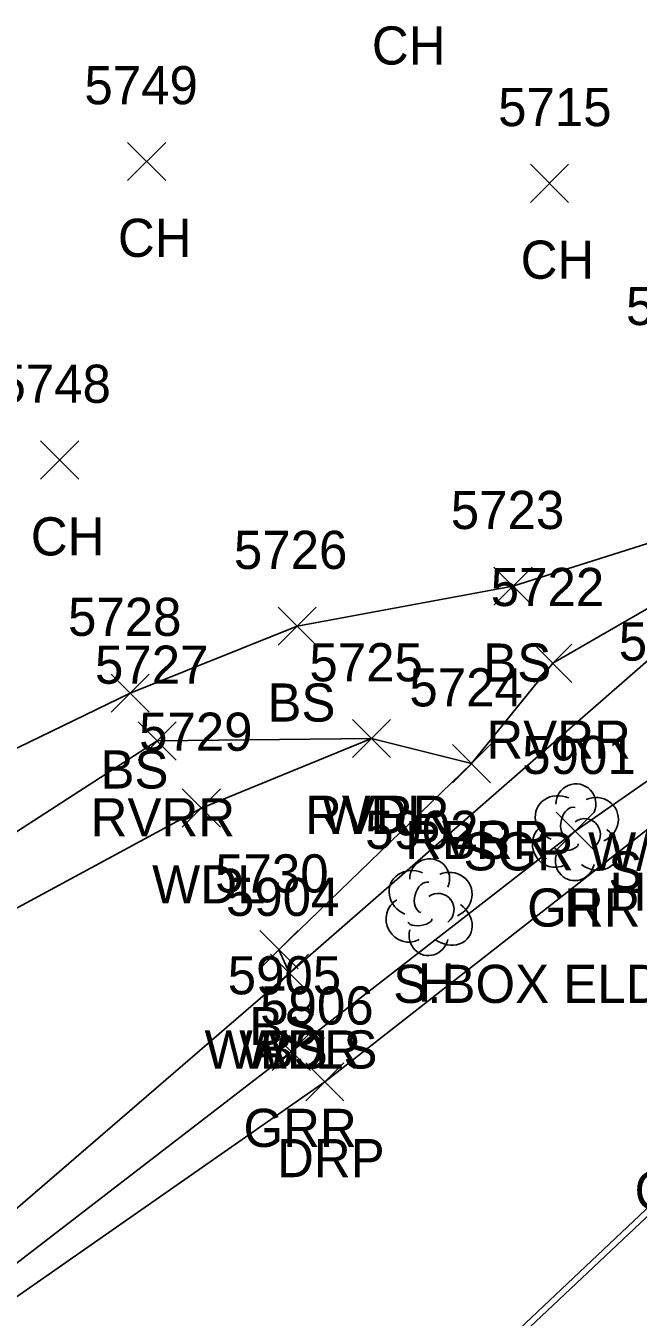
# Model space of a CAD drawing. Extents: x 1618146 to 1620418, y 640749 to 641927.
# Drawn here: x 1619997.9 to 1620030, y 641180.8 to 641248.4 of the extents above; entities that cross this region are included whole.
import ezdxf

# ---------------------------------------------------------------- set-up
doc = ezdxf.new("R2010")
doc.units = 0
for name, color, linetype in [('C_A', 7, 'Continuous'), ('L_A', 7, 'Continuous'), ('L_C', 7, 'Continuous'), ('L_I', 7, 'Continuous'), ('L_TIC', 7, 'Continuous'), ('LAWA', 7, 'Continuous'), ('LAWE', 7, 'Continuous'), ('LELB', 7, 'Continuous'), ('LS', 7, 'Continuous'), ('LTD', 7, 'Continuous'), ('LWS', 7, 'Continuous'), ('R_A', 7, 'Continuous'), ('R_C', 7, 'Continuous'), ('R_I', 7, 'Continuous'), ('R_TIC', 7, 'Continuous'), ('RDP', 7, 'Continuous'), ('RGR', 7, 'Continuous')]:
    doc.layers.add(name, color=color, linetype=linetype)

msp = doc.modelspace()

# ---------------------------------------------------------------- linework, layer by layer
at = {"layer": 'L_TIC'}
for points in [[(1620003.272, 641240.333), (1620005.272, 641242.333)], [(1620005.272, 641240.333), (1620003.272, 641242.333)], [(1620024.392, 641239.186), (1620026.392, 641241.186)], [(1620026.392, 641239.186), (1620024.392, 641241.186)], [(1619998.704, 641224.683), (1620000.704, 641226.683)], [(1620000.704, 641224.683), (1619998.704, 641226.683)], [(1620022.476, 641218.069), (1620024.476, 641220.069)], [(1620024.476, 641218.069), (1620022.476, 641220.069)], [(1620011.158, 641215.975), (1620013.158, 641217.975)], [(1620013.158, 641215.975), (1620011.158, 641217.975)], [(1620024.57, 641214.03), (1620026.57, 641216.03)], [(1620026.57, 641214.03), (1620024.57, 641216.03)], [(1620002.405, 641212.467), (1620004.405, 641214.467)], [(1620004.405, 641212.467), (1620002.405, 641214.467)], [(1620003.818, 641209.958), (1620005.818, 641211.958)], [(1620005.818, 641209.958), (1620003.818, 641211.958)], [(1620015.061, 641210.085), (1620017.061, 641212.085)], [(1620017.061, 641210.085), (1620015.061, 641212.085)], [(1620015.061, 641210.085), (1620017.061, 641212.085)], [(1620017.061, 641210.085), (1620015.061, 641212.085)], [(1620020.304, 641208.771), (1620022.304, 641210.771)], [(1620022.304, 641208.771), (1620020.304, 641210.771)], [(1620020.304, 641208.771), (1620022.304, 641210.771)], [(1620022.304, 641208.771), (1620020.304, 641210.771)], [(1620006.137, 641206.445), (1620008.137, 641208.445)], [(1620008.137, 641206.445), (1620006.137, 641208.445)], [(1620010.206, 641199.016), (1620012.206, 641201.016)], [(1620012.206, 641199.016), (1620010.206, 641201.016)], [(1620010.761, 641197.789), (1620012.761, 641199.789)], [(1620012.761, 641197.789), (1620010.761, 641199.789)], [(1620010.761, 641197.789), (1620012.761, 641199.789)], [(1620012.761, 641197.789), (1620010.761, 641199.789)], [(1620010.761, 641197.789), (1620012.761, 641199.789)], [(1620012.761, 641197.789), (1620010.761, 641199.789)]]:
    msp.add_lwpolyline(points, dxfattribs=at)
at = {"layer": 'LAWA'}
for points in [[(1620016.061, 641211.085), (1620007.137, 641207.445), (1619990.867, 641198.646), (1619979.489, 641190.047), (1619970.845, 641183.189), (1619962.87, 641173.915)], [(1620011.761, 641198.789), (1619992.673, 641182.338), (1619977.791, 641170.879), (1619968.517, 641161.582), (1619963.081, 641155.848), (1619963.663, 641145.429), (1619975.534, 641122.902)]]:
    msp.add_lwpolyline(points, dxfattribs=at)
at = {"layer": 'LAWE'}
msp.add_lwpolyline([(1620126.924, 641247.392), (1620111.117, 641239.46), (1620109.41, 641236.163), (1620101.636, 641234.759), (1620084.088, 641235.913), (1620071.67, 641229.784), (1620042.737, 641224.388), (1620037.792, 641222.07), (1620025.57, 641215.03), (1620021.304, 641209.771), (1620016.061, 641211.085), (1620004.818, 641210.958), (1619989.454, 641201.04), (1619976.614, 641195.505), (1619948.377, 641191.059)], dxfattribs=at)
at = {"layer": 'LELB'}
for points in [[(1620126.924, 641247.392), (1620111.61, 641247.659), (1620106.398, 641242.54), (1620098.527, 641237.323), (1620084.828, 641239.216), (1620069.098, 641232.991), (1620064.278, 641237.198), (1620039.166, 641227.389), (1620035.445, 641222.864), (1620023.476, 641219.069), (1620012.158, 641216.975), (1620003.405, 641213.467), (1619988.117, 641206.058), (1619975.419, 641196.769), (1619947.495, 641194.474)], [(1620021.304, 641209.771), (1620011.206, 641200.016), (1620011.761, 641198.789)]]:
    msp.add_lwpolyline(points, dxfattribs=at)
at = {"layer": 'LS'}
msp.add_lwpolyline([(1620044.169, 641182.771), (1620036.207, 641191.402), (1620015.554, 641171.939), (1620014.678, 641171.33), (1620022.603, 641162.294)], dxfattribs=at)
at = {"layer": 'LTD'}
for p, q in [((1620026.734, 641206.228), (1620026.734, 641206.228)), ((1620026.734, 641206.228), (1620026.734, 641206.228)), ((1620019.063, 641202.301), (1620019.063, 641202.301)), ((1620019.063, 641202.301), (1620019.063, 641202.301))]:
    msp.add_line(p, q, dxfattribs=at)
for centre in [(1620026.78, 641207.662), (1620019.109, 641203.735)]:
    msp.add_arc(centre, 1.047, 335.52715, 180.95627, dxfattribs=at)
for centre, major_axis, ratio, start_param, end_param in [((1620025.942, 641206.894), (1.21, -0.512), 0.895232, 1.570796, 4.712389), ((1620027.775, 641206.811), (-1.141, -0.483), 0.949671, 1.570796, 4.712389), ((1620026.525, 641206.686), (-0.208, -0.792), 0.645439, 3.141593, 6.283185), ((1620027.234, 641206.061), (-0.5, 0.667), 0.989748, 3.141593, 6.283185), ((1620025.65, 641205.519), (0.584, -1.042), 0.959034, 3.141593, 6.283185), ((1620027.734, 641205.394), (-1.09, 0.792), 0.841452, 1.570796, 4.712389), ((1620026.275, 641205.477), (-0.625, -0.083), 0.423636, 0, 3.141593), ((1620026.734, 641204.728), (0.265, 1.061), 0.942809, 1.570796, 4.712389), ((1620018.271, 641202.968), (1.21, -0.512), 0.895232, 1.570796, 4.712389), ((1620020.104, 641202.885), (-1.141, -0.483), 0.949671, 1.570796, 4.712389), ((1620018.854, 641202.759), (-0.208, -0.792), 0.645439, 3.141593, 6.283185), ((1620019.563, 641202.135), (-0.5, 0.667), 0.989748, 3.141593, 6.283185), ((1620017.979, 641201.593), (0.584, -1.042), 0.959034, 3.141593, 6.283185), ((1620020.063, 641201.468), (-1.09, 0.792), 0.841452, 1.570796, 4.712389), ((1620018.604, 641201.551), (-0.625, -0.083), 0.423636, 0, 3.141593), ((1620019.063, 641200.801), (0.265, 1.061), 0.942809, 1.570796, 4.712389)]:
    msp.add_ellipse(centre, major_axis=major_axis, ratio=ratio, start_param=start_param, end_param=end_param, dxfattribs=at)
at = {"layer": 'LWS'}
msp.add_lwpolyline([(1620048.672, 641217.648), (1620035.768, 641219.739), (1620011.761, 641198.789)], dxfattribs=at)
at = {"layer": 'R_TIC'}
for points in [[(1620025.734, 641205.228), (1620027.734, 641207.228)], [(1620027.734, 641205.228), (1620025.734, 641207.228)], [(1620010.856, 641193.678), (1620012.856, 641195.678)], [(1620012.856, 641193.678), (1620010.856, 641195.678)], [(1620012.614, 641192.094), (1620014.614, 641194.094)], [(1620014.614, 641192.094), (1620012.614, 641194.094)]]:
    msp.add_lwpolyline(points, dxfattribs=at)
at = {"layer": 'RDP'}
for points in [[(1620043.034, 641194.193), (1620044.893, 641206.844), (1620037.069, 641211.433), (1620013.614, 641193.094), (1619994.356, 641179.667), (1619979.096, 641167.968), (1619969.083, 641160.779), (1619967.434, 641155.411), (1619967.402, 641148.339), (1619978.796, 641124.54), (1619983.899, 641114.171)], [(1620043.034, 641194.193), (1620036.085, 641191.731), (1620015.329, 641172.126), (1620014.678, 641171.33)]]:
    msp.add_lwpolyline(points, dxfattribs=at)
at = {"layer": 'RGR'}
msp.add_lwpolyline([(1620036.714, 641213.174), (1620026.734, 641206.228), (1620011.856, 641194.678), (1619993.659, 641180.685), (1619978.562, 641168.865), (1619968.756, 641161.751), (1619965.702, 641155.687), (1619966.634, 641148.002), (1619978.242, 641124.494), (1619983.31, 641114)], dxfattribs=at)

# ---------------------------------------------------------------- texts
at = {"layer": 'C_A'}
msp.add_text('HVCTRL', height=2, dxfattribs=at).set_placement((1620028.546, 641202.059))
at = {"layer": 'L_A'}
for s, p in [('CH', (1620016.077, 641246.415)), ('CH', (1620002.76, 641236.333)), ('CH', (1620023.88, 641235.186)), ('CH', (1619998.192, 641220.683)), ('BS', (1620021.917, 641214.069)), ('BS', (1620010.599, 641211.975)), ('RVRR', (1620022.082, 641210.03)), ('BS', (1620001.846, 641208.467)), ('RVRR', (1620012.573, 641206.085)), ('WDL', (1620013.478, 641206.085)), ('RVRR', (1620001.329, 641205.958)), ('RVRR', (1620017.816, 641204.771)), ('BS', (1620019.745, 641204.771)), ('WDL', (1620004.554, 641202.445)), ('H', (1620026.167, 641201.228)), ('H', (1620018.496, 641197.301)), ('BS', (1620009.647, 641195.016)), ('WALLS', (1620007.305, 641193.789)), ('WDR', (1620009.123, 641193.789)), ('BS', (1620010.202, 641193.789)), ('CONCPAD', (1620029.852, 641186.402))]:
    msp.add_text(s, height=2, dxfattribs=at).set_placement(p)
at = {"layer": 'L_C'}
for s, p in [('S.ELM', (1620028.481, 641203.17)), ('S.BOX ELDER', (1620017.198, 641197.228))]:
    msp.add_text(s, height=2, dxfattribs=at).set_placement(p)
at = {"layer": 'L_I'}
for s, p in [('5749', (1620001.004, 641244.333)), ('5715', (1620022.699, 641243.186)), ('5716', (1620029.404, 641232.76)), ('5748', (1619996.444, 641228.683)), ('5723', (1620020.217, 641222.069)), ('5726', (1620008.844, 641219.975)), ('5722', (1620022.31, 641218.03)), ('5728', (1620000.145, 641216.467)), ('5900', (1620029.025, 641215.17)), ('5727', (1620001.558, 641213.958)), ('5725', (1620012.801, 641214.085)), ('5725', (1620012.801, 641214.085)), ('5724', (1620018.045, 641212.771)), ('5724', (1620018.045, 641212.771)), ('5729', (1620003.869, 641210.445)), ('5901', (1620023.962, 641209.228)), ('5902', (1620015.724, 641205.301)), ('5730', (1620007.859, 641203.016)), ('5904', (1620008.423, 641201.789)), ('5904', (1620008.423, 641201.789)), ('5904', (1620008.423, 641201.789))]:
    msp.add_text(s, height=2, dxfattribs=at).set_placement(p)
at = {"layer": 'R_A'}
for s, p in [('GRR', (1620024.222, 641201.228)), ('GRR', (1620009.344, 641189.678)), ('DRP', (1620011.103, 641188.094))]:
    msp.add_text(s, height=2, dxfattribs=at).set_placement(p)
at = {"layer": 'R_C'}
msp.add_text('SGR W/ STEEL POST', height=2, dxfattribs=at).set_placement((1620020.879, 641204.174))
at = {"layer": 'R_I'}
for s, p in [('5901', (1620023.962, 641209.228)), ('5905', (1620008.518, 641197.678)), ('5906', (1620010.221, 641196.094))]:
    msp.add_text(s, height=2, dxfattribs=at).set_placement(p)

doc.saveas('drawing.dxf')
